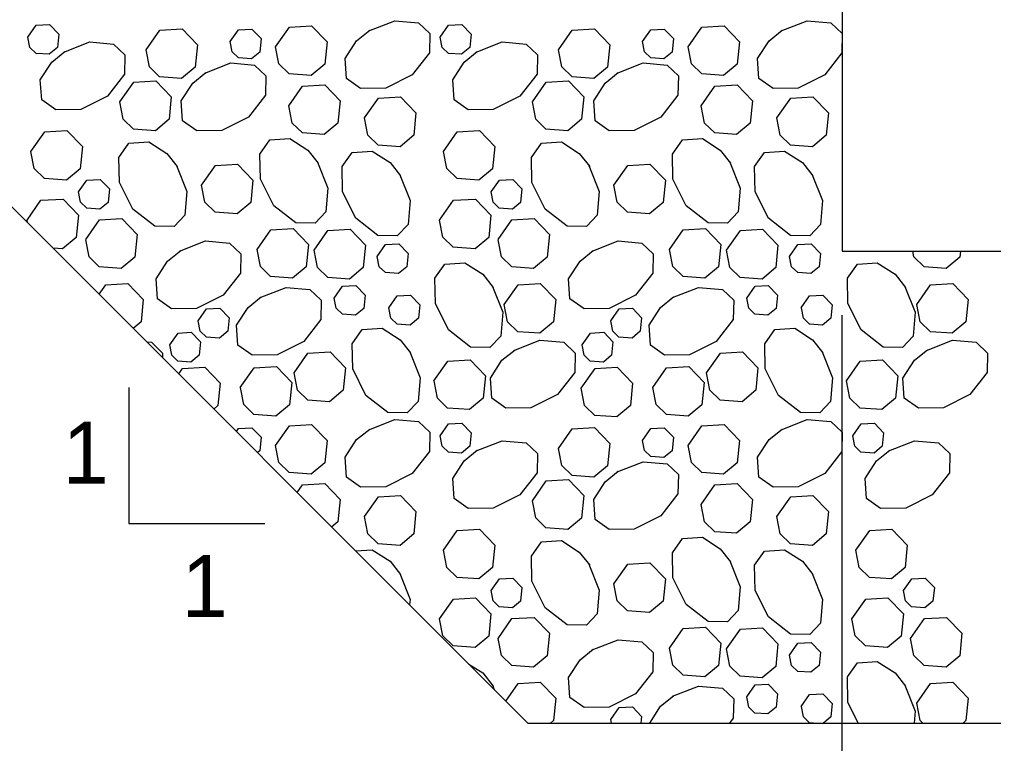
# Model space of a CAD drawing. Extents: x 638079 to 640019, y 297691 to 298879.
# Drawn here: x 639607.53 to 639654.74, y 298706.61 to 298741.68 of the extents above; entities that cross this region are included whole.
import ezdxf

# ---------------------------------------------------------------- set-up
doc = ezdxf.new("R2010")
doc.units = 0
doc.layers.add('1', color=7, linetype='Continuous')

msp = doc.modelspace()

# ---------------------------------------------------------------- linework, layer by layer
at = {"layer": '1'}
for p, q in [((639647.406, 298760.936), (639647.406, 298730.456)), ((639632.166, 298707.596), (639601.686, 298738.076)), ((639647.406, 298730.456), (639799.806, 298730.456)), ((639647.406, 298684.625), (639647.406, 298727.36)), ((639612.835, 298723.844), (639612.835, 298717.259)), ((639612.835, 298717.259), (639619.42, 298717.259)), ((639632.166, 298707.596), (639815.046, 298707.596))]:
    msp.add_line(p, q, dxfattribs=at)
for points in [[(639624.455, 298741.123), (639625.713, 298741.622), (639626.868, 298741.522), (639627.417, 298741), (639627.4, 298740.063), (639626.567, 298738.997), (639625.279, 298738.353), (639624.065, 298738.332), (639623.382, 298738.818), (639623.317, 298739.784), (639623.871, 298740.649), (639624.506, 298741.156)], [(639644.444, 298741.123), (639645.702, 298741.622), (639646.857, 298741.522), (639647.406, 298741)], [(639607.937, 298740.827), (639608.34, 298741.401), (639608.984, 298741.438), (639609.432, 298740.974), (639609.367, 298740.323), (639608.969, 298739.992), (639608.333, 298740.038), (639608.034, 298740.329), (639607.937, 298740.827)], [(639613.662, 298740.213), (639614.334, 298741.17), (639615.407, 298741.231), (639616.154, 298740.457), (639616.046, 298739.373), (639615.383, 298738.822), (639614.323, 298738.899), (639613.824, 298739.382), (639613.662, 298740.213)], [(639617.741, 298740.607), (639618.144, 298741.18), (639618.788, 298741.217), (639619.236, 298740.753), (639619.171, 298740.103), (639618.774, 298739.772), (639618.137, 298739.818), (639617.838, 298740.108), (639617.741, 298740.606)], [(639619.944, 298740.359), (639620.616, 298741.315), (639621.69, 298741.376), (639622.436, 298740.603), (639622.328, 298739.519), (639621.665, 298738.967), (639620.605, 298739.044), (639620.106, 298739.527), (639619.945, 298740.359)], [(639627.925, 298740.827), (639628.329, 298741.401), (639628.973, 298741.438), (639629.42, 298740.974), (639629.356, 298740.323), (639628.958, 298739.992), (639628.322, 298740.038), (639628.023, 298740.329), (639627.926, 298740.827)], [(639633.65, 298740.213), (639634.323, 298741.17), (639635.396, 298741.231), (639636.142, 298740.457), (639636.034, 298739.373), (639635.371, 298738.822), (639634.311, 298738.899), (639633.813, 298739.382), (639633.651, 298740.213)], [(639637.729, 298740.607), (639638.133, 298741.18), (639638.777, 298741.217), (639639.225, 298740.753), (639639.16, 298740.103), (639638.762, 298739.772), (639638.126, 298739.818), (639637.827, 298740.108), (639637.73, 298740.606)], [(639639.933, 298740.359), (639640.605, 298741.315), (639641.678, 298741.376), (639642.424, 298740.603), (639642.316, 298739.519), (639641.653, 298738.967), (639640.594, 298739.044), (639640.095, 298739.527), (639639.933, 298740.359)], [(639647.406, 298741), (639647.389, 298740.063), (639646.555, 298738.997), (639645.267, 298738.353), (639644.053, 298738.332), (639643.37, 298738.818), (639643.305, 298739.784), (639643.86, 298740.649), (639644.495, 298741.156)], [(639609.679, 298740.091), (639610.936, 298740.589), (639612.092, 298740.49), (639612.641, 298739.968), (639612.623, 298739.03), (639611.79, 298737.965), (639610.502, 298737.321), (639609.288, 298737.3), (639608.605, 298737.785), (639608.54, 298738.752), (639609.095, 298739.617), (639609.73, 298740.123)], [(639629.667, 298740.091), (639630.925, 298740.589), (639632.08, 298740.49), (639632.629, 298739.968), (639632.612, 298739.03), (639631.778, 298737.965), (639630.491, 298737.321), (639629.277, 298737.3), (639628.594, 298737.785), (639628.529, 298738.752), (639629.083, 298739.617), (639629.718, 298740.123)], [(639616.511, 298739.074), (639617.769, 298739.573), (639618.924, 298739.473), (639619.473, 298738.951), (639619.456, 298738.013), (639618.622, 298736.948), (639617.334, 298736.304), (639616.121, 298736.283), (639615.437, 298736.768), (639615.373, 298737.735), (639615.927, 298738.6), (639616.562, 298739.106)], [(639636.5, 298739.074), (639637.757, 298739.573), (639638.913, 298739.473), (639639.462, 298738.951), (639639.444, 298738.013), (639638.611, 298736.948), (639637.323, 298736.304), (639636.109, 298736.283), (639635.426, 298736.768), (639635.361, 298737.735), (639635.916, 298738.6), (639636.551, 298739.106)], [(639612.397, 298737.683), (639613.069, 298738.64), (639614.142, 298738.701), (639614.889, 298737.927), (639614.781, 298736.843), (639614.118, 298736.292), (639613.058, 298736.369), (639612.559, 298736.852), (639612.397, 298737.683)], [(639620.577, 298737.496), (639621.249, 298738.452), (639622.322, 298738.513), (639623.068, 298737.74), (639622.96, 298736.656), (639622.297, 298736.104), (639621.238, 298736.181), (639620.739, 298736.664), (639620.577, 298737.496)], [(639632.385, 298737.683), (639633.058, 298738.64), (639634.131, 298738.701), (639634.877, 298737.927), (639634.769, 298736.843), (639634.106, 298736.292), (639633.046, 298736.369), (639632.548, 298736.852), (639632.386, 298737.683)], [(639640.565, 298737.496), (639641.237, 298738.452), (639642.311, 298738.513), (639643.057, 298737.74), (639642.949, 298736.656), (639642.286, 298736.104), (639641.226, 298736.181), (639640.728, 298736.664), (639640.566, 298737.496)], [(639624.252, 298736.91), (639624.924, 298737.866), (639625.998, 298737.928), (639626.744, 298737.154), (639626.636, 298736.07), (639625.973, 298735.518), (639624.913, 298735.595), (639624.415, 298736.079), (639624.253, 298736.91)], [(639644.241, 298736.91), (639644.913, 298737.866), (639645.986, 298737.928), (639646.732, 298737.154), (639646.624, 298736.07), (639645.961, 298735.518), (639644.902, 298735.595), (639644.403, 298736.079), (639644.241, 298736.91)], [(639608.086, 298735.284), (639608.758, 298736.24), (639609.831, 298736.301), (639610.578, 298735.528), (639610.47, 298734.444), (639609.807, 298733.892), (639608.747, 298733.969), (639608.248, 298734.453), (639608.086, 298735.284)], [(639628.074, 298735.284), (639628.747, 298736.24), (639629.82, 298736.301), (639630.566, 298735.528), (639630.458, 298734.444), (639629.795, 298733.892), (639628.735, 298733.969), (639628.237, 298734.453), (639628.075, 298735.284)], [(639615.143, 298734.609), (639615.642, 298733.351), (639615.542, 298732.196), (639615.02, 298731.646), (639614.082, 298731.664), (639613.017, 298732.497), (639612.373, 298733.785), (639612.352, 298734.999), (639612.837, 298735.682), (639613.804, 298735.747), (639614.669, 298735.193), (639615.175, 298734.558)], [(639621.976, 298734.771), (639622.474, 298733.514), (639622.374, 298732.358), (639621.852, 298731.809), (639620.915, 298731.827), (639619.85, 298732.66), (639619.206, 298733.948), (639619.184, 298735.162), (639619.67, 298735.845), (639620.637, 298735.91), (639621.501, 298735.356), (639622.008, 298734.721)], [(639635.131, 298734.609), (639635.63, 298733.351), (639635.53, 298732.196), (639635.008, 298731.646), (639634.071, 298731.664), (639633.006, 298732.497), (639632.362, 298733.785), (639632.34, 298734.999), (639632.826, 298735.682), (639633.793, 298735.747), (639634.657, 298735.193), (639635.164, 298734.558)], [(639641.964, 298734.771), (639642.463, 298733.514), (639642.363, 298732.358), (639641.841, 298731.809), (639640.903, 298731.827), (639639.838, 298732.66), (639639.194, 298733.948), (639639.173, 298735.162), (639639.658, 298735.845), (639640.625, 298735.91), (639641.49, 298735.356), (639641.996, 298734.721)], [(639625.961, 298734.161), (639626.46, 298732.904), (639626.36, 298731.748), (639625.838, 298731.199), (639624.901, 298731.217), (639623.835, 298732.05), (639623.192, 298733.338), (639623.17, 298734.552), (639623.656, 298735.235), (639624.622, 298735.3), (639625.487, 298734.746), (639625.994, 298734.111)], [(639645.95, 298734.161), (639646.448, 298732.904), (639646.349, 298731.748), (639645.827, 298731.199), (639644.889, 298731.217), (639643.824, 298732.05), (639643.18, 298733.338), (639643.159, 298734.552), (639643.644, 298735.235), (639644.611, 298735.3), (639645.476, 298734.746), (639645.982, 298734.111)], [(639616.351, 298733.657), (639617.023, 298734.614), (639618.096, 298734.675), (639618.843, 298733.901), (639618.735, 298732.817), (639618.072, 298732.266), (639617.012, 298732.342), (639616.513, 298732.826), (639616.351, 298733.657)], [(639636.339, 298733.657), (639637.011, 298734.614), (639638.085, 298734.675), (639638.831, 298733.901), (639638.723, 298732.817), (639638.06, 298732.266), (639637, 298732.342), (639636.502, 298732.826), (639636.34, 298733.657)], [(639610.396, 298733.324), (639610.799, 298733.898), (639611.443, 298733.935), (639611.891, 298733.471), (639611.826, 298732.82), (639611.428, 298732.489), (639610.792, 298732.536), (639610.493, 298732.826), (639610.396, 298733.324)], [(639630.384, 298733.324), (639630.788, 298733.898), (639631.432, 298733.935), (639631.879, 298733.471), (639631.815, 298732.82), (639631.417, 298732.489), (639630.781, 298732.536), (639630.482, 298732.826), (639630.385, 298733.324)], [(639607.898, 298731.963), (639608.57, 298732.919), (639609.643, 298732.981), (639610.389, 298732.207), (639610.281, 298731.123), (639609.618, 298730.571), (639609.157, 298730.605)], [(639627.886, 298731.963), (639628.558, 298732.919), (639629.632, 298732.981), (639630.378, 298732.207), (639630.27, 298731.123), (639629.607, 298730.571), (639628.547, 298730.648), (639628.048, 298731.132), (639627.887, 298731.963)], [(639607.922, 298731.84), (639607.898, 298731.963)], [(639610.738, 298731.014), (639611.411, 298731.97), (639612.484, 298732.031), (639613.23, 298731.258), (639613.122, 298730.173), (639612.459, 298729.622), (639611.399, 298729.699), (639610.901, 298730.182), (639610.739, 298731.013)], [(639630.727, 298731.014), (639631.399, 298731.97), (639632.472, 298732.031), (639633.219, 298731.258), (639633.111, 298730.173), (639632.448, 298729.622), (639631.388, 298729.699), (639630.889, 298730.182), (639630.727, 298731.013)], [(639619.041, 298730.54), (639619.713, 298731.496), (639620.787, 298731.557), (639621.533, 298730.784), (639621.425, 298729.7), (639620.762, 298729.148), (639619.702, 298729.225), (639619.204, 298729.708), (639619.042, 298730.539)], [(639621.807, 298730.499), (639622.479, 298731.455), (639623.552, 298731.517), (639624.299, 298730.743), (639624.191, 298729.659), (639623.527, 298729.107), (639622.468, 298729.184), (639621.969, 298729.668), (639621.807, 298730.499)], [(639639.03, 298730.54), (639639.702, 298731.496), (639640.775, 298731.557), (639641.521, 298730.784), (639641.413, 298729.7), (639640.75, 298729.148), (639639.691, 298729.225), (639639.192, 298729.708), (639639.03, 298730.539)], [(639641.795, 298730.499), (639642.467, 298731.455), (639643.541, 298731.517), (639644.287, 298730.743), (639644.179, 298729.659), (639643.516, 298729.107), (639642.456, 298729.184), (639641.958, 298729.668), (639641.796, 298730.499)], [(639615.291, 298730.452), (639616.549, 298730.951), (639617.704, 298730.851), (639618.253, 298730.329), (639618.236, 298729.391), (639617.402, 298728.326), (639616.114, 298727.682), (639614.901, 298727.661), (639614.217, 298728.146), (639614.153, 298729.113), (639614.707, 298729.978), (639615.342, 298730.484)], [(639624.866, 298730.204), (639625.269, 298730.777), (639625.913, 298730.814), (639626.361, 298730.35), (639626.296, 298729.7), (639625.898, 298729.369), (639625.262, 298729.415), (639624.963, 298729.705), (639624.866, 298730.203)], [(639635.28, 298730.452), (639636.537, 298730.951), (639637.693, 298730.851), (639638.242, 298730.329), (639638.224, 298729.391), (639637.391, 298728.326), (639636.103, 298727.682), (639634.889, 298727.661), (639634.206, 298728.146), (639634.141, 298729.113), (639634.696, 298729.978), (639635.33, 298730.484)], [(639644.854, 298730.204), (639645.257, 298730.777), (639645.902, 298730.814), (639646.349, 298730.35), (639646.284, 298729.7), (639645.887, 298729.369), (639645.251, 298729.415), (639644.951, 298729.705), (639644.854, 298730.203)], [(639653.128, 298730.456), (639653.099, 298730.173), (639652.436, 298729.622), (639651.376, 298729.699), (639650.878, 298730.182), (639650.824, 298730.456)], [(639630.454, 298728.752), (639630.953, 298727.495), (639630.853, 298726.339), (639630.331, 298725.79), (639629.394, 298725.808), (639628.328, 298726.641), (639627.685, 298727.929), (639627.663, 298729.143), (639628.149, 298729.826), (639629.116, 298729.891), (639629.98, 298729.336), (639630.487, 298728.701)], [(639650.443, 298728.752), (639650.942, 298727.495), (639650.842, 298726.339), (639650.32, 298725.79), (639649.382, 298725.808), (639648.317, 298726.641), (639647.673, 298727.929), (639647.652, 298729.143), (639648.137, 298729.826), (639649.104, 298729.891), (639649.969, 298729.336), (639650.475, 298728.701)], [(639611.391, 298728.371), (639611.71, 298728.824), (639612.783, 298728.885), (639613.529, 298728.111), (639613.421, 298727.027), (639613.047, 298726.715)], [(639631.026, 298727.867), (639631.698, 298728.824), (639632.772, 298728.885), (639633.518, 298728.111), (639633.41, 298727.027), (639632.747, 298726.476), (639631.687, 298726.552), (639631.188, 298727.036), (639631.026, 298727.867)], [(639651.014, 298727.867), (639651.687, 298728.824), (639652.76, 298728.885), (639653.506, 298728.111), (639653.398, 298727.027), (639652.735, 298726.476), (639651.675, 298726.552), (639651.177, 298727.036), (639651.015, 298727.867)], [(639619.193, 298728.206), (639620.451, 298728.704), (639621.606, 298728.604), (639622.155, 298728.082), (639622.138, 298727.145), (639621.304, 298726.079), (639620.016, 298725.436), (639618.803, 298725.414), (639618.119, 298725.9), (639618.055, 298726.867), (639618.609, 298727.731), (639619.244, 298728.238)], [(639622.785, 298728.186), (639623.188, 298728.76), (639623.832, 298728.797), (639624.28, 298728.332), (639624.215, 298727.682), (639623.817, 298727.351), (639623.181, 298727.397), (639622.882, 298727.687), (639622.785, 298728.186)], [(639639.181, 298728.206), (639640.439, 298728.704), (639641.594, 298728.604), (639642.144, 298728.082), (639642.126, 298727.145), (639641.293, 298726.079), (639640.005, 298725.436), (639638.791, 298725.414), (639638.108, 298725.9), (639638.043, 298726.867), (639638.597, 298727.731), (639639.232, 298728.238)], [(639642.773, 298728.186), (639643.177, 298728.76), (639643.821, 298728.797), (639644.268, 298728.332), (639644.204, 298727.682), (639643.806, 298727.351), (639643.17, 298727.397), (639642.871, 298727.687), (639642.774, 298728.186)], [(639625.433, 298727.713), (639625.836, 298728.287), (639626.48, 298728.324), (639626.928, 298727.859), (639626.863, 298727.209), (639626.466, 298726.878), (639625.83, 298726.924), (639625.53, 298727.214), (639625.433, 298727.713)], [(639645.421, 298727.713), (639645.825, 298728.287), (639646.469, 298728.324), (639646.917, 298727.859), (639646.852, 298727.209), (639646.454, 298726.878), (639645.818, 298726.924), (639645.519, 298727.214), (639645.422, 298727.713)], [(639616.196, 298727.083), (639616.6, 298727.657), (639617.244, 298727.693), (639617.691, 298727.229), (639617.627, 298726.579), (639617.229, 298726.248), (639616.593, 298726.294), (639616.294, 298726.584), (639616.197, 298727.083)], [(639636.185, 298727.083), (639636.588, 298727.657), (639637.232, 298727.693), (639637.68, 298727.229), (639637.615, 298726.579), (639637.217, 298726.248), (639636.581, 298726.294), (639636.282, 298726.584), (639636.185, 298727.083)], [(639614.809, 298725.916), (639615.213, 298726.49), (639615.857, 298726.527), (639616.304, 298726.063), (639616.24, 298725.412), (639615.842, 298725.081), (639615.206, 298725.127), (639614.907, 298725.417), (639614.81, 298725.916)], [(639626.449, 298725.58), (639626.948, 298724.322), (639626.848, 298723.167), (639626.326, 298722.618), (639625.388, 298722.635), (639624.323, 298723.469), (639623.679, 298724.757), (639623.658, 298725.97), (639624.143, 298726.654), (639625.11, 298726.718), (639625.975, 298726.164), (639626.481, 298725.529)], [(639634.798, 298725.916), (639635.201, 298726.49), (639635.845, 298726.527), (639636.293, 298726.063), (639636.228, 298725.412), (639635.83, 298725.081), (639635.194, 298725.127), (639634.895, 298725.417), (639634.798, 298725.916)], [(639646.437, 298725.58), (639646.936, 298724.322), (639646.836, 298723.167), (639646.314, 298722.618), (639645.377, 298722.635), (639644.311, 298723.469), (639643.668, 298724.757), (639643.646, 298725.97), (639644.132, 298726.654), (639645.099, 298726.718), (639645.963, 298726.164), (639646.47, 298725.529)], [(639613.701, 298726.061), (639613.92, 298726.042), (639614.469, 298725.52), (639614.465, 298725.297)], [(639631.496, 298725.644), (639632.754, 298726.142), (639633.909, 298726.042), (639634.458, 298725.52), (639634.44, 298724.583), (639633.607, 298723.518), (639632.319, 298722.874), (639631.105, 298722.852), (639630.422, 298723.338), (639630.357, 298724.305), (639630.912, 298725.169), (639631.547, 298725.676)], [(639651.484, 298725.644), (639652.742, 298726.142), (639653.897, 298726.042), (639654.446, 298725.52), (639654.429, 298724.583), (639653.595, 298723.518), (639652.308, 298722.874), (639651.094, 298722.852), (639650.411, 298723.338), (639650.346, 298724.305), (639650.9, 298725.169), (639651.535, 298725.676)], [(639620.84, 298724.555), (639621.512, 298725.512), (639622.586, 298725.573), (639623.332, 298724.799), (639623.224, 298723.715), (639622.561, 298723.164), (639621.501, 298723.241), (639621.003, 298723.724), (639620.841, 298724.555)], [(639640.829, 298724.555), (639641.501, 298725.512), (639642.574, 298725.573), (639643.321, 298724.799), (639643.213, 298723.715), (639642.549, 298723.164), (639641.49, 298723.241), (639640.991, 298723.724), (639640.829, 298724.555)], [(639627.619, 298724.169), (639628.291, 298725.126), (639629.365, 298725.187), (639630.111, 298724.413), (639630.003, 298723.329), (639629.34, 298722.778), (639628.28, 298722.854), (639627.781, 298723.338), (639627.62, 298724.169)], [(639647.607, 298724.169), (639648.28, 298725.126), (639649.353, 298725.187), (639650.099, 298724.413), (639649.991, 298723.329), (639649.328, 298722.778), (639648.268, 298722.854), (639647.77, 298723.338), (639647.608, 298724.169)], [(639615.253, 298724.509), (639615.437, 298724.771), (639616.51, 298724.832), (639617.256, 298724.059), (639617.148, 298722.974), (639616.952, 298722.81)], [(639618.233, 298723.854), (639618.905, 298724.81), (639619.979, 298724.872), (639620.725, 298724.098), (639620.617, 298723.014), (639619.954, 298722.462), (639618.894, 298722.539), (639618.395, 298723.023), (639618.234, 298723.854)], [(639634.753, 298723.815), (639635.425, 298724.771), (639636.499, 298724.832), (639637.245, 298724.059), (639637.137, 298722.974), (639636.474, 298722.423), (639635.414, 298722.5), (639634.915, 298722.983), (639634.754, 298723.814)], [(639638.221, 298723.854), (639638.894, 298724.81), (639639.967, 298724.872), (639640.713, 298724.098), (639640.605, 298723.014), (639639.942, 298722.462), (639638.882, 298722.539), (639638.384, 298723.023), (639638.222, 298723.854)], [(639624.455, 298721.809), (639625.713, 298722.307), (639626.868, 298722.208), (639627.417, 298721.686), (639627.4, 298720.748), (639626.567, 298719.683), (639625.279, 298719.039), (639624.065, 298719.018), (639623.382, 298719.503), (639623.317, 298720.47), (639623.871, 298721.335), (639624.506, 298721.841)], [(639644.444, 298721.809), (639645.702, 298722.307), (639646.857, 298722.208), (639647.406, 298721.686), (639647.389, 298720.748), (639646.555, 298719.683), (639645.267, 298719.039), (639644.053, 298719.018), (639643.37, 298719.503), (639643.305, 298720.47), (639643.86, 298721.335), (639644.495, 298721.841)], [(639618.042, 298721.72), (639618.144, 298721.866), (639618.788, 298721.903), (639619.236, 298721.438), (639619.171, 298720.788), (639619.064, 298720.698)], [(639619.944, 298721.044), (639620.616, 298722.001), (639621.69, 298722.062), (639622.436, 298721.288), (639622.328, 298720.204), (639621.665, 298719.653), (639620.605, 298719.729), (639620.106, 298720.213), (639619.945, 298721.044)], [(639627.925, 298721.513), (639628.329, 298722.087), (639628.973, 298722.123), (639629.42, 298721.659), (639629.356, 298721.009), (639628.958, 298720.678), (639628.322, 298720.724), (639628.023, 298721.014), (639627.926, 298721.513)], [(639633.65, 298720.899), (639634.323, 298721.855), (639635.396, 298721.917), (639636.142, 298721.143), (639636.034, 298720.059), (639635.371, 298719.507), (639634.311, 298719.584), (639633.813, 298720.068), (639633.651, 298720.899)], [(639637.729, 298721.292), (639638.133, 298721.866), (639638.777, 298721.903), (639639.225, 298721.438), (639639.16, 298720.788), (639638.762, 298720.457), (639638.126, 298720.503), (639637.827, 298720.793), (639637.73, 298721.292)], [(639639.933, 298721.044), (639640.605, 298722.001), (639641.678, 298722.062), (639642.424, 298721.288), (639642.316, 298720.204), (639641.653, 298719.653), (639640.594, 298719.729), (639640.095, 298720.213), (639639.933, 298721.044)], [(639647.914, 298721.513), (639648.317, 298722.087), (639648.961, 298722.123), (639649.409, 298721.659), (639649.344, 298721.009), (639648.946, 298720.678), (639648.31, 298720.724), (639648.011, 298721.014), (639647.914, 298721.513)], [(639629.667, 298720.776), (639630.925, 298721.275), (639632.08, 298721.175), (639632.629, 298720.653), (639632.612, 298719.716), (639631.778, 298718.65), (639630.491, 298718.006), (639629.277, 298717.985), (639628.594, 298718.471), (639628.529, 298719.437), (639629.083, 298720.302), (639629.718, 298720.809)], [(639649.656, 298720.776), (639650.913, 298721.275), (639652.069, 298721.175), (639652.618, 298720.653), (639652.6, 298719.716), (639651.767, 298718.65), (639650.479, 298718.006), (639649.265, 298717.985), (639648.582, 298718.471), (639648.517, 298719.437), (639649.072, 298720.302), (639649.707, 298720.809)], [(639636.5, 298719.76), (639637.757, 298720.258), (639638.913, 298720.158), (639639.462, 298719.636), (639639.444, 298718.699), (639638.611, 298717.634), (639637.323, 298716.99), (639636.109, 298716.968), (639635.426, 298717.454), (639635.361, 298718.421), (639635.916, 298719.285), (639636.551, 298719.792)], [(639620.991, 298718.771), (639621.249, 298719.138), (639622.322, 298719.199), (639623.068, 298718.425), (639622.96, 298717.341), (639622.666, 298717.096)], [(639632.385, 298718.369), (639633.058, 298719.325), (639634.131, 298719.387), (639634.877, 298718.613), (639634.769, 298717.529), (639634.106, 298716.977), (639633.046, 298717.054), (639632.548, 298717.538), (639632.386, 298718.369)], [(639640.565, 298718.181), (639641.237, 298719.138), (639642.311, 298719.199), (639643.057, 298718.425), (639642.949, 298717.341), (639642.286, 298716.79), (639641.226, 298716.866), (639640.728, 298717.35), (639640.566, 298718.181)], [(639624.252, 298717.596), (639624.924, 298718.552), (639625.998, 298718.613), (639626.744, 298717.84), (639626.636, 298716.756), (639625.973, 298716.204), (639624.913, 298716.281), (639624.415, 298716.764), (639624.253, 298717.595)], [(639644.241, 298717.596), (639644.913, 298718.552), (639645.986, 298718.613), (639646.732, 298717.84), (639646.624, 298716.756), (639645.961, 298716.204), (639644.902, 298716.281), (639644.403, 298716.764), (639644.241, 298717.595)], [(639628.074, 298715.969), (639628.747, 298716.926), (639629.82, 298716.987), (639630.566, 298716.213), (639630.458, 298715.129), (639629.795, 298714.578), (639628.735, 298714.654), (639628.237, 298715.138), (639628.075, 298715.969)], [(639641.964, 298715.457), (639642.463, 298714.199), (639642.363, 298713.044), (639641.841, 298712.495), (639640.903, 298712.512), (639639.838, 298713.346), (639639.194, 298714.634), (639639.173, 298715.847), (639639.658, 298716.531), (639640.625, 298716.595), (639641.49, 298716.041), (639641.996, 298715.406)], [(639648.063, 298715.969), (639648.735, 298716.926), (639649.808, 298716.987), (639650.555, 298716.213), (639650.447, 298715.129), (639649.784, 298714.578), (639648.724, 298714.654), (639648.225, 298715.138), (639648.063, 298715.969)], [(639635.131, 298715.294), (639635.63, 298714.037), (639635.53, 298712.881), (639635.008, 298712.332), (639634.071, 298712.35), (639633.006, 298713.183), (639632.362, 298714.471), (639632.34, 298715.685), (639632.826, 298716.368), (639633.793, 298716.432), (639634.657, 298715.878), (639635.164, 298715.243)], [(639623.83, 298715.932), (639624.622, 298715.985), (639625.487, 298715.431), (639625.994, 298714.796)], [(639645.95, 298714.847), (639646.448, 298713.589), (639646.349, 298712.434), (639645.827, 298711.885), (639644.889, 298711.902), (639643.824, 298712.736), (639643.18, 298714.024), (639643.159, 298715.237), (639643.644, 298715.921), (639644.611, 298715.985), (639645.476, 298715.431), (639645.982, 298714.796)], [(639636.339, 298714.343), (639637.011, 298715.299), (639638.085, 298715.36), (639638.831, 298714.587), (639638.723, 298713.503), (639638.06, 298712.951), (639637, 298713.028), (639636.502, 298713.511), (639636.34, 298714.343)], [(639625.961, 298714.847), (639626.46, 298713.589), (639626.437, 298713.325)], [(639630.384, 298714.01), (639630.788, 298714.584), (639631.432, 298714.621), (639631.879, 298714.156), (639631.815, 298713.506), (639631.417, 298713.175), (639630.781, 298713.221), (639630.482, 298713.511), (639630.385, 298714.01)], [(639650.373, 298714.01), (639650.776, 298714.584), (639651.42, 298714.621), (639651.868, 298714.156), (639651.803, 298713.506), (639651.405, 298713.175), (639650.769, 298713.221), (639650.47, 298713.511), (639650.373, 298714.01)], [(639627.886, 298712.649), (639628.558, 298713.605), (639629.632, 298713.666), (639630.378, 298712.893), (639630.27, 298711.808), (639629.607, 298711.257), (639628.547, 298711.334), (639628.048, 298711.817), (639627.887, 298712.648)], [(639647.875, 298712.649), (639648.547, 298713.605), (639649.62, 298713.666), (639650.366, 298712.893), (639650.258, 298711.808), (639649.595, 298711.257), (639648.535, 298711.334), (639648.037, 298711.817), (639647.875, 298712.648)], [(639630.727, 298711.699), (639631.399, 298712.655), (639632.472, 298712.717), (639633.219, 298711.943), (639633.111, 298710.859), (639632.448, 298710.307), (639631.388, 298710.384), (639630.889, 298710.868), (639630.727, 298711.699)], [(639650.715, 298711.699), (639651.388, 298712.655), (639652.461, 298712.717), (639653.207, 298711.943), (639653.099, 298710.859), (639652.436, 298710.307), (639651.376, 298710.384), (639650.878, 298710.868), (639650.716, 298711.699)], [(639639.03, 298711.225), (639639.702, 298712.182), (639640.775, 298712.243), (639641.521, 298711.469), (639641.413, 298710.385), (639640.75, 298709.834), (639639.691, 298709.91), (639639.192, 298710.394), (639639.03, 298711.225)], [(639641.795, 298711.184), (639642.467, 298712.141), (639643.541, 298712.202), (639644.287, 298711.428), (639644.179, 298710.344), (639643.516, 298709.793), (639642.456, 298709.87), (639641.958, 298710.353), (639641.796, 298711.184)], [(639635.28, 298711.138), (639636.537, 298711.636), (639637.693, 298711.536), (639638.242, 298711.014), (639638.224, 298710.077), (639637.391, 298709.012), (639636.103, 298708.368), (639634.889, 298708.346), (639634.206, 298708.832), (639634.141, 298709.799), (639634.696, 298710.663), (639635.33, 298711.17)], [(639644.854, 298710.889), (639645.257, 298711.463), (639645.902, 298711.5), (639646.349, 298711.035), (639646.284, 298710.385), (639645.887, 298710.054), (639645.251, 298710.1), (639644.951, 298710.39), (639644.854, 298710.889)], [(639648.182, 298707.596), (639647.673, 298708.614), (639647.652, 298709.828), (639648.137, 298710.511), (639649.104, 298710.576), (639649.969, 298710.022), (639650.475, 298709.387)], [(639629.311, 298710.451), (639629.98, 298710.022), (639630.487, 298709.387)], [(639631.102, 298708.66), (639631.698, 298709.509), (639632.772, 298709.57), (639633.518, 298708.797), (639633.41, 298707.713), (639633.27, 298707.596)], [(639651.014, 298708.553), (639651.687, 298709.509), (639652.76, 298709.57), (639653.506, 298708.797), (639653.398, 298707.713), (639653.258, 298707.596)], [(639630.454, 298709.438), (639630.54, 298709.222)], [(639639.181, 298708.891), (639640.439, 298709.39), (639641.594, 298709.29), (639642.144, 298708.768), (639642.126, 298707.83), (639641.943, 298707.596)], [(639642.773, 298708.871), (639643.177, 298709.445), (639643.821, 298709.482), (639644.268, 298709.018), (639644.204, 298708.367), (639643.806, 298708.036), (639643.17, 298708.083), (639642.871, 298708.373), (639642.774, 298708.871)], [(639650.443, 298709.438), (639650.942, 298708.18), (639650.891, 298707.596)], [(639638.072, 298707.596), (639638.597, 298708.417), (639639.232, 298708.923)], [(639645.421, 298708.399), (639645.825, 298708.972), (639646.469, 298709.009), (639646.917, 298708.545), (639646.852, 298707.895), (639646.493, 298707.596)], [(639636.185, 298707.768), (639636.588, 298708.342), (639637.232, 298708.379), (639637.68, 298707.915), (639637.648, 298707.596)], [(639646.005, 298707.596), (639645.818, 298707.61), (639645.519, 298707.9), (639645.422, 298708.398)], [(639651.306, 298707.596), (639651.177, 298707.721), (639651.015, 298708.553)], [(639636.219, 298707.596), (639636.185, 298707.768)]]:
    msp.add_lwpolyline(points, dxfattribs=at)

# ---------------------------------------------------------------- texts
for p in [(639609.622, 298719.191), (639615.392, 298712.73)]:
    msp.add_text('1', height=3, dxfattribs=at).set_placement(p)

doc.saveas('drawing.dxf')
